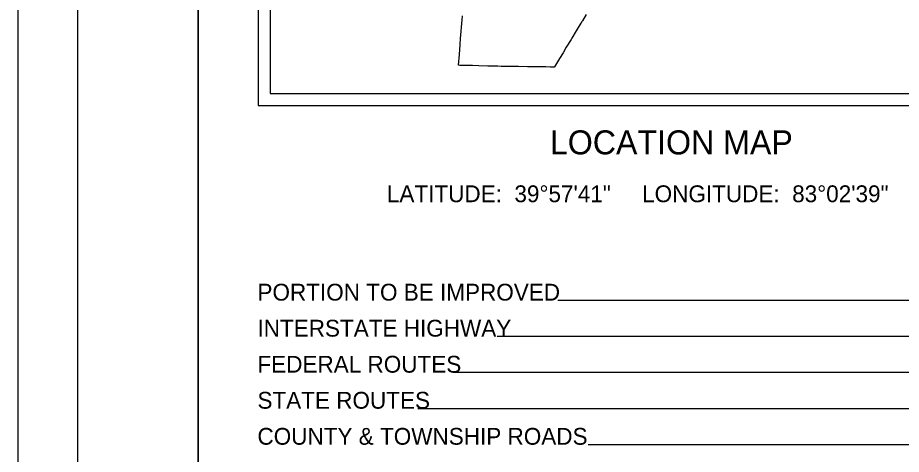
# Model space of a CAD drawing. Extents: x 0 to 34, y 0 to 22.
# Drawn here: x 0 to 7.35, y 11.1 to 14.73 of the extents above; entities that cross this region are included whole.
import ezdxf

# ---------------------------------------------------------------- set-up
doc = ezdxf.new("R2010")
doc.units = 0
for name, color, linetype in [('GM_X_County', 7, 'Continuous'), ('SH_Border', 7, 'Continuous'), ('SH_Cut_Line', 7, 'Continuous'), ('SH_Data', 7, 'Continuous'), ('SH_Text', 7, 'Continuous')]:
    doc.layers.add(name, color=color, linetype=linetype)

msp = doc.modelspace()

# ---------------------------------------------------------------- linework, layer by layer
at = {"layer": 'GM_X_County'}
msp.add_lwpolyline([(4.7276, 14.7572), (4.6974, 14.7063), (4.6968, 14.7054), (4.6959, 14.7039), (4.6938, 14.7005), (4.6907, 14.6952), (4.686, 14.6874), (4.685, 14.6858), (4.6849, 14.6856), (4.6848, 14.6855), (4.6846, 14.6854), (4.6845, 14.6853), (4.6844, 14.6853), (4.6844, 14.6853), (4.6842, 14.6852), (4.6465, 14.6228), (4.6095, 14.5616), (4.6089, 14.5605), (4.6026, 14.55), (4.5636, 14.4853), (4.5363, 14.4398), (4.5082, 14.3933), (4.4657, 14.3225), (4.4644, 14.3203), (4.4556, 14.3205), (4.4324, 14.3208), (4.3929, 14.3214), (4.3686, 14.3217), (4.3296, 14.3223), (4.273, 14.3232), (4.2411, 14.3236), (4.2395, 14.3237), (4.1648, 14.3247), (4.1009, 14.3257), (4.0212, 14.3268), (3.9934, 14.3275), (3.9553, 14.3284), (3.9098, 14.3295), (3.8352, 14.3313), (3.7825, 14.3326), (3.7303, 14.3338), (3.6765, 14.3351), (3.667, 14.3353), (3.674, 14.4259), (3.6742, 14.4278), (3.6801, 14.5039), (3.6804, 14.5081), (3.6844, 14.5596), (3.6965, 14.7149), (3.699, 14.7483)], dxfattribs=at)
at = {"layer": 'SH_Border'}
for points in [[(0.5, 21.5), (1.5, 21.5), (1.5, 0.5), (0.5, 0.5)], [(1.5, 21.5), (33.5, 21.5), (33.5, 0.5), (1.5, 0.5)]]:
    msp.add_lwpolyline(points, close=True, dxfattribs=at)
at = {"layer": 'SH_Cut_Line'}
msp.add_lwpolyline([(0, 0), (34, 0), (34, 22), (0, 22)], close=True, dxfattribs=at)
at = {"layer": 'SH_Data'}
for p, q in [((2, 21), (2, 14)), ((2.1, 20.9), (2.1, 14.1)), ((2.1, 14.1), (8.9, 14.1)), ((2.1, 14.1), (2.1, 14.1)), ((2, 14), (9, 14)), ((7.7, 12.3767), (4.4937, 12.3767)), ((7.7, 12.0767), (3.9895, 12.0767)), ((7.7, 11.7767), (3.6192, 11.7767)), ((7.7, 11.4767), (3.3288, 11.4767)), ((7.7, 11.1767), (4.7452, 11.1767))]:
    msp.add_line(p, q, dxfattribs=at)

# ---------------------------------------------------------------- texts
at = {"layer": 'SH_Text'}
for s, height, p in [('LOCATION MAP', 0.2, (4.4269, 13.5938)), ('LATITUDE:  39°57\'41"     LONGITUDE:  83°02\'39"', 0.14, (3.071, 13.1959)), ('PORTION TO BE IMPROVED', 0.14, (1.9944, 12.3767)), ('INTERSTATE HIGHWAY', 0.14, (1.9944, 12.0767)), ('FEDERAL ROUTES', 0.14, (1.9944, 11.7767)), ('STATE ROUTES', 0.14, (1.9944, 11.4767)), ('COUNTY & TOWNSHIP ROADS', 0.14, (1.9944, 11.1767))]:
    msp.add_text(s, height=height, dxfattribs=at).set_placement(p)

doc.saveas('drawing.dxf')
